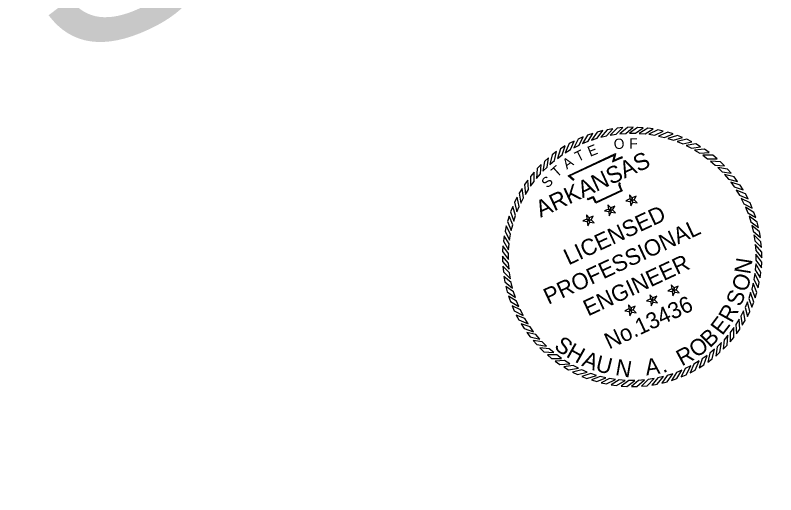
# Model space of a CAD drawing. Extents: x 756526 to 763735, y 1656374 to 1661090.
# Drawn here: x 758848 to 759548, y 1659146 to 1659588 of the extents above; entities that cross this region are included whole.
import ezdxf

# ---------------------------------------------------------------- set-up
doc = ezdxf.new("R2010")
doc.units = 0
doc.layers.add('1', color=7, linetype='Continuous')
doc.layers.add('G-ANNO-SYMB', color=7, linetype='Continuous')

msp = doc.modelspace()

# ---------------------------------------------------------------- linework, layer by layer
at = {"layer": 'G-ANNO-SYMB'}
for points in [[(759398.26, 1659483.23), (759393.2, 1659482.35), (759387.26, 1659475.4), (759392.66, 1659476.67)], [(759407.57, 1659484.27), (759402.46, 1659483.79), (759395.99, 1659477.33), (759401.47, 1659478.18)], [(759416.93, 1659484.58), (759411.8, 1659484.5), (759404.85, 1659478.56), (759410.37, 1659478.98)], [(759426.29, 1659484.16), (759421.17, 1659484.48), (759413.77, 1659479.1), (759419.31, 1659479.09)], [(759435.59, 1659483), (759430.51, 1659483.72), (759422.71, 1659478.94), (759428.24, 1659478.49)], [(759371.21, 1659475.79), (759366.5, 1659473.75), (759362.35, 1659465.6), (759367.3, 1659468.11)], [(759380.02, 1659478.98), (759375.17, 1659477.32), (759370.39, 1659469.52), (759375.52, 1659471.62)], [(759389.06, 1659481.46), (759384.09, 1659480.19), (759378.71, 1659472.79), (759383.99, 1659474.49)], [(759444.76, 1659481.11), (759439.76, 1659482.23), (759431.61, 1659478.08), (759437.08, 1659477.19)], [(759453.77, 1659478.51), (759448.86, 1659480.02), (759440.41, 1659476.52), (759445.8, 1659475.21)], [(759462.53, 1659475.21), (759457.76, 1659477.1), (759449.07, 1659474.28), (759454.33, 1659472.55)], [(759362.68, 1659471.92), (759358.14, 1659469.52), (759354.65, 1659461.07), (759359.38, 1659463.95)], [(759471.02, 1659471.24), (759466.41, 1659473.49), (759457.52, 1659471.36), (759462.63, 1659469.22)], [(759479.16, 1659466.61), (759474.75, 1659469.22), (759465.72, 1659467.79), (759470.65, 1659465.26)], [(759346.65, 1659462.24), (759342.55, 1659459.16), (759340.42, 1659450.27), (759344.64, 1659453.85)], [(759354.48, 1659467.39), (759350.14, 1659464.65), (759347.32, 1659455.95), (759351.81, 1659459.19)], [(759486.92, 1659461.35), (759482.72, 1659464.3), (759473.61, 1659463.59), (759478.32, 1659460.67)], [(759339.26, 1659456.48), (759335.41, 1659453.09), (759333.98, 1659444.06), (759337.91, 1659447.97)], [(759494.24, 1659455.5), (759490.29, 1659458.78), (759481.14, 1659458.78), (759485.62, 1659455.5)], [(759332.34, 1659450.17), (759328.77, 1659446.49), (759328.05, 1659437.37), (759331.66, 1659441.57)], [(759501.08, 1659449.1), (759497.4, 1659452.67), (759488.28, 1659453.39), (759492.48, 1659449.78)], [(759325.94, 1659443.33), (759322.67, 1659439.38), (759322.67, 1659430.23), (759325.94, 1659434.71)], [(759507.4, 1659442.18), (759504, 1659446.03), (759494.97, 1659447.46), (759498.88, 1659443.53)], [(759513.15, 1659434.79), (759510.07, 1659438.89), (759501.18, 1659441.03), (759504.76, 1659436.8)], [(759320.09, 1659436.01), (759317.14, 1659431.81), (759317.86, 1659422.69), (759320.77, 1659427.41)], [(759518.31, 1659426.97), (759515.56, 1659431.3), (759506.86, 1659434.13), (759510.1, 1659429.63)], [(759314.84, 1659428.25), (759312.22, 1659423.84), (759313.65, 1659414.8), (759316.19, 1659419.73)], [(759522.83, 1659418.76), (759520.43, 1659423.3), (759511.98, 1659426.8), (759514.86, 1659422.06)], [(759310.21, 1659420.11), (759307.95, 1659415.5), (759310.08, 1659406.61), (759312.22, 1659411.72)], [(759415.87, 1659417.55), (759416.27, 1659419.59), (759413.57, 1659422.49), (759414.05, 1659418.56)], [(759415.87, 1659417.55), (759417.94, 1659417.8), (759419.86, 1659421.27), (759416.27, 1659419.59)], [(759396.1, 1659408.33), (759396.49, 1659410.37), (759393.79, 1659413.27), (759394.28, 1659409.34)], [(759415.87, 1659417.55), (759414.05, 1659418.56), (759410.46, 1659416.88), (759414.35, 1659416.13)], [(759415.87, 1659417.55), (759414.35, 1659416.13), (759414.83, 1659412.19), (759416.75, 1659415.66)], [(759415.87, 1659417.55), (759416.75, 1659415.66), (759420.64, 1659414.9), (759417.94, 1659417.8)], [(759526.7, 1659410.23), (759524.66, 1659414.94), (759516.52, 1659419.09), (759519.02, 1659414.14)], [(759306.23, 1659411.62), (759304.34, 1659406.85), (759307.17, 1659398.16), (759308.9, 1659403.42)], [(759396.1, 1659408.33), (759394.28, 1659409.34), (759390.68, 1659407.66), (759394.57, 1659406.91)], [(759396.1, 1659408.33), (759394.57, 1659406.91), (759395.06, 1659402.97), (759396.98, 1659406.44)], [(759396.1, 1659408.33), (759398.17, 1659408.58), (759400.09, 1659412.05), (759396.49, 1659410.37)], [(759396.1, 1659408.33), (759396.98, 1659406.44), (759400.87, 1659405.68), (759398.17, 1659408.58)], [(759529.89, 1659401.42), (759528.23, 1659406.27), (759520.43, 1659411.05), (759522.53, 1659405.92)], [(759302.93, 1659402.85), (759301.42, 1659397.95), (759304.92, 1659389.5), (759306.23, 1659394.89)], [(759376.32, 1659399.11), (759374.5, 1659400.12), (759370.91, 1659398.44), (759374.8, 1659397.69)], [(759376.32, 1659399.11), (759376.72, 1659401.15), (759374.02, 1659404.05), (759374.5, 1659400.12)], [(759376.32, 1659399.11), (759374.8, 1659397.69), (759375.28, 1659393.75), (759377.2, 1659397.22)], [(759376.32, 1659399.11), (759378.39, 1659399.36), (759380.31, 1659402.83), (759376.72, 1659401.15)], [(759376.32, 1659399.11), (759377.2, 1659397.22), (759381.09, 1659396.46), (759378.39, 1659399.36)], [(759532.37, 1659392.39), (759531.1, 1659397.36), (759523.7, 1659402.73), (759525.4, 1659397.45)], [(759300.33, 1659393.85), (759299.21, 1659388.85), (759303.36, 1659380.7), (759304.25, 1659386.17)], [(759534.14, 1659383.19), (759533.26, 1659388.24), (759526.31, 1659394.18), (759527.59, 1659388.79)], [(759298.45, 1659384.68), (759297.72, 1659379.6), (759302.5, 1659371.8), (759302.95, 1659377.32)], [(759535.18, 1659373.88), (759534.7, 1659378.98), (759528.24, 1659385.45), (759529.09, 1659379.97)], [(759297.29, 1659375.38), (759296.96, 1659370.26), (759302.34, 1659362.86), (759302.36, 1659368.4)], [(759535.49, 1659364.51), (759535.42, 1659369.64), (759529.48, 1659376.6), (759529.89, 1659371.07)], [(759296.86, 1659366.02), (759296.94, 1659360.89), (759302.88, 1659353.94), (759302.46, 1659359.46)], [(759535.07, 1659355.15), (759535.39, 1659360.27), (759530.02, 1659367.67), (759530, 1659362.13)], [(759297.17, 1659356.66), (759297.65, 1659351.55), (759304.12, 1659345.08), (759303.27, 1659350.56)], [(759533.91, 1659345.86), (759534.63, 1659350.93), (759529.85, 1659358.73), (759529.4, 1659353.21)], [(759532.02, 1659336.68), (759533.14, 1659341.69), (759528.99, 1659349.83), (759528.11, 1659344.36)], [(759298.21, 1659347.35), (759299.09, 1659342.29), (759306.05, 1659336.35), (759304.77, 1659341.75)], [(759299.98, 1659338.15), (759301.25, 1659333.17), (759308.65, 1659327.8), (759306.96, 1659333.08)], [(759454.48, 1659334.74), (759452.66, 1659335.75), (759449.07, 1659334.08), (759452.96, 1659333.32)], [(759454.48, 1659334.74), (759454.88, 1659336.79), (759452.18, 1659339.69), (759452.66, 1659335.75)], [(759454.48, 1659334.74), (759456.55, 1659335), (759458.47, 1659338.46), (759454.88, 1659336.79)], [(759529.42, 1659327.68), (759530.93, 1659332.58), (759527.43, 1659341.03), (759526.12, 1659335.64)], [(759302.47, 1659329.11), (759304.13, 1659324.26), (759311.92, 1659319.48), (759309.82, 1659324.61)], [(759434.71, 1659325.52), (759435.11, 1659327.57), (759432.4, 1659330.47), (759432.89, 1659326.53)], [(759434.71, 1659325.52), (759436.78, 1659325.78), (759438.7, 1659329.24), (759435.11, 1659327.57)], [(759454.48, 1659334.74), (759452.96, 1659333.32), (759453.44, 1659329.39), (759455.36, 1659332.86)], [(759454.48, 1659334.74), (759455.36, 1659332.86), (759459.25, 1659332.1), (759456.55, 1659335)], [(759526.12, 1659318.91), (759528.01, 1659323.68), (759525.19, 1659332.38), (759523.46, 1659327.11)], [(759434.71, 1659325.52), (759432.89, 1659326.53), (759429.3, 1659324.86), (759433.19, 1659324.1)], [(759434.71, 1659325.52), (759433.19, 1659324.1), (759433.67, 1659320.17), (759435.59, 1659323.63)], [(759434.71, 1659325.52), (759435.59, 1659323.63), (759439.48, 1659322.88), (759436.78, 1659325.78)], [(759522.15, 1659310.43), (759524.41, 1659315.03), (759522.27, 1659323.92), (759520.13, 1659318.81)], [(759305.65, 1659320.3), (759307.69, 1659315.59), (759315.84, 1659311.44), (759313.34, 1659316.39)], [(759414.94, 1659316.3), (759413.11, 1659317.31), (759409.52, 1659315.64), (759413.41, 1659314.88)], [(759414.94, 1659316.3), (759415.33, 1659318.35), (759412.63, 1659321.25), (759413.11, 1659317.31)], [(759414.94, 1659316.3), (759413.41, 1659314.88), (759413.89, 1659310.95), (759415.82, 1659314.41)], [(759414.94, 1659316.3), (759417, 1659316.56), (759418.92, 1659320.02), (759415.33, 1659318.35)], [(759414.94, 1659316.3), (759415.82, 1659314.41), (759419.71, 1659313.66), (759417, 1659316.56)], [(759517.52, 1659302.28), (759520.13, 1659306.7), (759518.7, 1659315.73), (759516.17, 1659310.8)], [(759309.52, 1659311.77), (759311.92, 1659307.23), (759320.37, 1659303.73), (759317.49, 1659308.47)], [(759512.26, 1659294.52), (759515.22, 1659298.72), (759514.5, 1659307.84), (759511.59, 1659303.12)], [(759314.05, 1659303.57), (759316.8, 1659299.23), (759325.49, 1659296.41), (759322.25, 1659300.9)], [(759319.2, 1659295.74), (759322.28, 1659291.64), (759331.18, 1659289.5), (759327.59, 1659293.73)], [(759506.42, 1659287.2), (759509.69, 1659291.15), (759509.69, 1659300.3), (759506.42, 1659295.83)], [(759324.96, 1659288.35), (759328.35, 1659284.5), (759337.38, 1659283.07), (759333.48, 1659287)], [(759500.01, 1659280.36), (759503.59, 1659284.05), (759504.3, 1659293.16), (759500.69, 1659288.96)], [(759331.27, 1659281.43), (759334.96, 1659277.86), (759344.07, 1659277.14), (759339.87, 1659280.75)], [(759485.7, 1659268.29), (759489.8, 1659271.37), (759491.94, 1659280.26), (759487.71, 1659276.68)], [(759493.09, 1659274.05), (759496.94, 1659277.44), (759498.37, 1659286.47), (759494.44, 1659282.56)], [(759338.11, 1659275.03), (759342.07, 1659271.75), (759351.21, 1659271.75), (759346.74, 1659275.03)], [(759477.88, 1659263.14), (759482.21, 1659265.88), (759485.04, 1659274.58), (759480.54, 1659271.34)], [(759345.43, 1659269.18), (759349.63, 1659266.23), (759358.75, 1659266.95), (759354.03, 1659269.86)], [(759469.67, 1659258.61), (759474.21, 1659261.01), (759477.71, 1659269.46), (759472.97, 1659266.58)], [(759353.19, 1659263.93), (759357.61, 1659261.31), (759366.64, 1659262.74), (759361.71, 1659265.27)], [(759361.34, 1659259.3), (759365.94, 1659257.04), (759374.84, 1659259.17), (759369.72, 1659261.31)], [(759452.33, 1659251.56), (759457.19, 1659253.22), (759461.96, 1659261.01), (759456.84, 1659258.91)], [(759461.14, 1659254.74), (759465.85, 1659256.78), (759470, 1659264.93), (759465.06, 1659262.43)], [(759369.82, 1659255.32), (759374.59, 1659253.43), (759383.29, 1659256.26), (759378.02, 1659257.99)], [(759378.59, 1659252.02), (759383.49, 1659250.51), (759391.94, 1659254.01), (759386.56, 1659255.32)], [(759387.59, 1659249.42), (759392.6, 1659248.3), (759400.75, 1659252.45), (759395.27, 1659253.34)], [(759396.77, 1659247.54), (759401.85, 1659246.81), (759409.64, 1659251.59), (759404.12, 1659252.04)], [(759415.42, 1659245.95), (759420.55, 1659246.03), (759427.51, 1659251.97), (759421.98, 1659251.55)], [(759424.79, 1659246.26), (759429.9, 1659246.74), (759436.36, 1659253.2), (759430.88, 1659252.36)], [(759434.1, 1659247.3), (759439.15, 1659248.18), (759445.09, 1659255.13), (759439.7, 1659253.86)], [(759443.3, 1659249.07), (759448.27, 1659250.34), (759453.64, 1659257.74), (759448.37, 1659256.05)], [(759406.06, 1659246.38), (759411.18, 1659246.05), (759418.58, 1659251.43), (759413.04, 1659251.44)]]:
    msp.add_lwpolyline(points, close=True, dxfattribs=at)
for points in [[(759362.25, 1659435.67), (759357.19, 1659439.96), (759400.79, 1659460.32), (759399.28, 1659454.04), (759402.23, 1659455.46), (759404.69, 1659456.65), (759407.29, 1659457.53)], [(759362.75, 1659436.26), (759358.59, 1659439.77), (759399.68, 1659458.96), (759398.17, 1659452.66), (759402.56, 1659454.78), (759404.98, 1659455.94), (759407.53, 1659456.81)], [(759404.32, 1659433.69), (759403.75, 1659432.51), (759403.97, 1659431.19), (759404.81, 1659428.72), (759405.92, 1659426.36), (759382.95, 1659415.65), (759381.37, 1659419.03), (759380.71, 1659420.44), (759378.91, 1659420.19), (759375.72, 1659418.7), (759375.02, 1659419.14)], [(759405, 1659433.35), (759404.54, 1659432.4), (759404.71, 1659431.38), (759405.52, 1659429), (759406.93, 1659425.99), (759382.58, 1659414.64), (759380.68, 1659418.71), (759380.26, 1659419.61), (759379.13, 1659419.45), (759375.67, 1659417.84), (759374.61, 1659418.49)]]:
    msp.add_lwpolyline(points, dxfattribs=at)

# ---------------------------------------------------------------- texts
at = {"layer": '1'}
msp.add_text('PASTE SCALE = 1250', height=200, rotation=25, dxfattribs=at).set_placement((758026.33, 1659137.05))
at = {"layer": 'G-ANNO-SYMB'}
for s, height, rotation, p in [('E', 9.49, 21.67203, (759377.47, 1659457.32)), ('O', 9.49, 6.2218, (759399.74, 1659464.11)), ('F', 9.49, 0.36282, (759413.45, 1659464.98)), ('T', 9.49, 26.47887, (759366.34, 1659452.45)), ('ARKANSAS', 15.494, 25, (759331.87, 1659401.16)), ('A', 9.49, 33.67877, (759356.03, 1659445.55)), ('T', 9.49, 41.90148, (759346.85, 1659437.95)), ('S', 9.49, 44.77256, (759338.2, 1659427.94)), ('LICENSED', 15, 25, (759357.6, 1659357.36)), ('PROFESSIONAL', 15.0001, 25, (759339.07, 1659321.04)), ('ENGINEER', 15, 25, (759375.57, 1659310.38)), ('N', 15, 81.10067, (759524.81, 1659348.76)), ('O', 15, 69.77573, (759521.08, 1659332.12)), ('No.13436', 14.941, 25, (759394.97, 1659279.97)), ('S', 15, 68.48784, (759515.94, 1659318.75)), ('R', 15, 60.65967, (759507.75, 1659303.68)), ('E', 15, 52.83149, (759499.07, 1659292.3)), ('B', 15, 43.88501, (759487.63, 1659280.98)), ('S', 15, 323.16364, (759343.42, 1659281.47)), ('O', 15, 36.42961, (759475.34, 1659271.74)), ('H', 15, 330.61905, (759354.58, 1659273.7)), ('R', 15, 28.22866, (759461.85, 1659264.38)), ('A', 15, 338.44722, (759369, 1659265.32)), ('U', 15, 345.90262, (759381.61, 1659260.41)), ('N', 15, 349.93262, (759400.03, 1659256.67)), ('A', 15, 8.09908, (759429.16, 1659256.06)), ('.', 15, 16.30002, (759444.37, 1659258.33))]:
    msp.add_text(s, height=height, rotation=rotation, dxfattribs=at).set_placement(p)

doc.saveas('drawing.dxf')
